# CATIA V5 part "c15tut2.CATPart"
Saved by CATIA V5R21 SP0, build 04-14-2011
Part number: Part1
Bounding box of the stored display mesh (mm): x -53 to 53, y -20 to 21, z -12 to 52
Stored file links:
  D:\CATIA V5R21 E-RESOURCES\CATIA-V5R21\catia-v5r21-prt\c15-catia-v5r20-prt\c15-catia-v5r21-tut02.CATPart
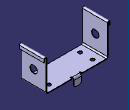
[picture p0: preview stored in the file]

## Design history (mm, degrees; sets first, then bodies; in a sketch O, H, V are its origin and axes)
SheetMetalParameters1: Thickness 1, BendRadius 2, KFactor 0.400515 {= log(min(100,max(20*SheetMetalParameters1.BendRadius,SheetMetalParameters1.Thickness)/SheetMetalParameters1.Thickness))/log(100)/2}, ReliefRadialLength 1, ReliefAxialLength 2, MinimumBendRadius 0
Body1 (main body)
  Sketch1 on xy-plane, origin (0, 0, 0), H (1, 0, 0), V (0, 1, 0)
    line L1 (50, 20) -> (50, -20)
    line L2 (50, -20) -> (-50, -20)
    line L3 (-50, -20) -> (-50, 20)
    line L4 (-50, 20) -> (50, 20)
    length L4 = 100
    length L1 = 40
    vertical: L1 V, L3 V
    horizontal: L2 H, L4 H
    equidistance: L1 L3 O, L2 L4 O
  Wall1: Thickness 1, Profile Sketch1
  Sketch2 on face of Wall1, origin (29.2419, -0.5458, 1), H (1, 0, 0), V (0, 1, 0)
    point P1 (-64.2419, -9.4542)
    reference projected line E1 (-79.2419, -19.4542) -> (-79.2419, 20.5458) from edge [face of Wall1 | face of Wall1]
    reference projected line E2 (20.7581, -19.4542) -> (-79.2419, -19.4542) from edge [face of Wall1 | face of Wall1]
    distance E1 P1 = 15
    distance E2 P1 = 10
  Hole1: placed by Sketch2, at (-35, -10, 1) direction (0, 0, -1), diameter 6, depth 10
  RectPattern1: of Hole1, direction 1 instances 2, spacing 70, along edge [face of Wall1 | face of Wall1] reversed, direction 2 instances 2, spacing 20, along edge [face of Wall1 | face of Wall1]
  Flange1: Angle 90, Length 50, Radius 2, KFacteur 0.400515 {= log(min(100,max(20*Flange1.Radius,SheetMetalParameters1.Thickness)/SheetMetalParameters1.Thickness))/log(100)/2}, Guide edge [face of Wall1 | face of Wall1]
  Flange2: Angle 90, Length 50, Radius 2, KFacteur 0.400515 {= log(min(100,max(20*Flange2.Radius,SheetMetalParameters1.Thickness)/SheetMetalParameters1.Thickness))/log(100)/2}, Guide edge [face of Wall1 | face of Wall1]
  Flange3: Angle 90, Length 5, Radius 1, KFacteur 0.325257 {= log(min(100,max(20*Flange3.Radius,SheetMetalParameters1.Thickness)/SheetMetalParameters1.Thickness))/log(100)/2}, Guide edge [face of Flange2 | face of Flange2]
  Flange4: Angle 90, Length 5, Radius 1, KFacteur 0.325257 {= log(min(100,max(20*Flange4.Radius,SheetMetalParameters1.Thickness)/SheetMetalParameters1.Thickness))/log(100)/2}, Guide edge [face of Flange1 | face of Flange1]
  Sketch3 on face of Flange1, origin (50, 0, 0), H (0, 1, 0), V (0, 0, 1)
    arc A1 centre (0, 25) radius 6 from (-1, 30.9161) to (1, 30.9161) ccw
    point P1 (0, 25)
    line L1 (-1, 30.9161) -> (-1, 29.9161)
    line L2 (-1, 29.9161) -> (1, 29.9161)
    line L3 (1, 29.9161) -> (1, 30.9161)
    radius A1 = 6
    distance H P1 = 25
    length L2 = 2
    distance V L1 = 1
    length L3 = 1
    coincidence: P1 V
    vertical: L1 V, L3 V
    horizontal: L2 H
  CutOut1: Direction Sketch3, EndLimit through (limit type 3), Orientation true, Profile Sketch3, StartLimit through (limit type 2)
  d_NewWallOnEdge1: NewWallOnEdge_Edge edge [face of Wall1 | face of Wall1], NewWallOnEdge_Length 13, NewWallOnEdge_HeightLimitOffset 0, NewWallOnEdge_WidthOffset1 -41, NewWallOnEdge_WidthOffset2 -41, NewWallOnEdge_Angle 90, NewWallOnEdge_BendRadiusValue 2 {= SheetMetalParameters1.BendRadius}, KFacteur 0.400515 {= log(min(100,max(20*d_NewWallOnEdge1.Radius,SheetMetalParameters1.Thickness)/SheetMetalParameters1.Thickness))/log(100)/2}
  Corner1: CornerRadius 3, CornerChamferEdges (edge [face of d_NewWallOnEdge1 | face of d_NewWallOnEdge1]; edge [face of d_NewWallOnEdge1 | face of d_NewWallOnEdge1])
